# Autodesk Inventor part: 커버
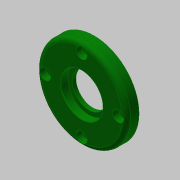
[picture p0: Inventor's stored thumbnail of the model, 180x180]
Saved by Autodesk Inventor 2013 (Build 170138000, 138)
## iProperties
Created: 2019-09
Part Number: 커버
Material: 알루미늄 6061
Document SubType Name: Modeling
Designer: mduedu
Density: 1 g/cm^3
Author: mduedu
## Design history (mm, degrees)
sketch "스케치1"
  geometry: C1 r 32 at (0, 0); 1 further point
  constraints: 1 centre point, 1 coincident
  dimensions: "d0" = 64 diameter of C1
extrude "돌출1" new body sketch "스케치1" distance "d1" = 9; taper "d2" = 0 deg
sketch "스케치2"
  geometry: C1 r 21 at (0, 0); 1 further point
  constraints: 1 centre point, 1 coincident
  dimensions: "d3" = 42 diameter of C1
extrude "돌출2" join sketch "스케치2" distance "d4" = 3; taper "d5" = 0 deg
hole "구멍1" diameter "d8" = 24; stored, may be unused: countersink angle "d12" = 90 deg, drill point angle "d14" = 118 deg; dims "d6" = 10, "d7" = 10, "d9" = 6, "d10" = 30, "d11" = 5.2, "d13" = 8
hole "구멍2" diameter "d17" = 37; stored, may be unused: countersink angle "d21" = 90 deg, drill point angle "d23" = 0 deg; dims "d15" = 10, "d16" = 10, "d18" = 6, "d19" = 30, "d20" = 5.2, "d22" = 4
fillet "모깎기1" dims "d24" = 3
fillet "모깎기2" dims "d25" = 3
chamfer "모따기1" distance "d27" = 0.5; stored, may be unused: second distance "d28" = 2, angle "d29" = 30 deg
chamfer "모따기2" distance "d30" = 1; stored, may be unused: second distance "d31" = 2, angle "d32" = 30 deg
sketch "스케치3" dims "d33" = 52
  geometry: 3 further points
  constraints: 2 vertical alignment, 1 coincident, 2 other
hole "구멍3" sketch "스케치3" at (0, 26) diameter "d34" = 4.5; stored, may be unused: countersink angle "d38" = 90 deg, drill point angle "d40" = 0 deg; dims "d35" = 6, "d36" = 8, "d37" = 4.4, "d39" = 4
node "솔리드1"
pattern_circular "원형 패턴1" dims angle "d42" = 360 deg
